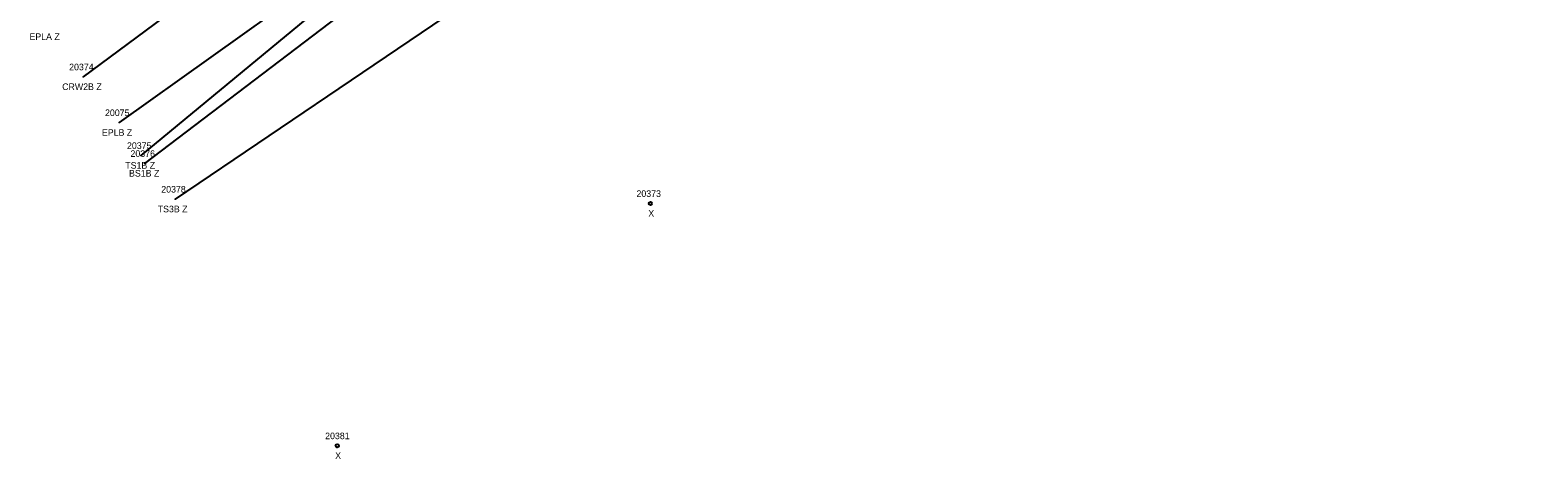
# Model space of a CAD drawing. Extents: x 1813127 to 1814107, y 1178171 to 1179078.
# Drawn here: x 1813574.7 to 1813803.8, y 1178408.6 to 1178473.8 of the extents above; entities that cross this region are included whole.
import ezdxf

# ---------------------------------------------------------------- set-up
doc = ezdxf.new("R2010")
doc.units = 0
for name, color, linetype in [('RD_DTM_BkLn1', 7, 'Continuous'), ('RD_DTM_BkLn2', 7, 'Continuous'), ('RD_EX_Road', 7, 'Continuous'), ('RD_EX_Road_txCode', 7, 'Continuous'), ('RD_SMD_Locator', 7, 'Continuous'), ('RD_SMD_Misc', 7, 'Continuous')]:
    doc.layers.add(name, color=color, linetype=linetype)

msp = doc.modelspace()

# ---------------------------------------------------------------- linework, layer by layer
at = {"layer": 'RD_DTM_BkLn1'}
msp.add_lwpolyline([(1813831.28, 1178643.33), (1813821.11, 1178637.41), (1813809.78, 1178629.12), (1813788.78, 1178614.79), (1813747.67, 1178586.85), (1813706.5, 1178558.14), (1813665.11, 1178528), (1813623.37, 1178496.83), (1813582.75, 1178466.66)], dxfattribs=at)
at = {"layer": 'RD_DTM_BkLn2'}
for points in [[(1813746.03, 1178561.9), (1813743.83, 1178564.42), (1813716.29, 1178544.93), (1813674.06, 1178515.49), (1813631.05, 1178487.38), (1813591.54, 1178454.7)], [(1813744.11, 1178561.57), (1813717.38, 1178543.56), (1813675.31, 1178513.46), (1813633, 1178484.68), (1813592.1, 1178453.49)], [(1813777.22, 1178536.25), (1813747.77, 1178553.49), (1813723.22, 1178536.36), (1813683.91, 1178504.3), (1813639.44, 1178476.94), (1813596.75, 1178448.06)]]:
    msp.add_lwpolyline(points, dxfattribs=at)
at = {"layer": 'RD_EX_Road'}
msp.add_lwpolyline([(1813815.99, 1178618.51), (1813795.14, 1178605.39), (1813756.93, 1178582.36), (1813736.74, 1178567), (1813712.58, 1178549.43), (1813670.71, 1178519.43), (1813630, 1178489.55), (1813588.23, 1178459.7)], dxfattribs=at)
at = {"layer": 'RD_SMD_Locator'}
for centre, radius in [((1813582.75, 1178466.66), 0.001), ((1813588.23, 1178459.7), 0.001), ((1813591.54, 1178454.7), 0.001), ((1813592.1, 1178453.49), 0.001), ((1813596.75, 1178448.06), 0.001), ((1813668.94, 1178447.4), 0.25), ((1813621.36, 1178410.56), 0.25)]:
    msp.add_circle(centre, radius, dxfattribs=at)

# ---------------------------------------------------------------- texts
at = {"layer": 'RD_EX_Road_txCode'}
for s, p in [('EPLA Z', (1813574.6, 1178472.27)), ('20075', (1813586.08, 1178460.7)), ('EPLB Z', (1813585.61, 1178457.7))]:
    msp.add_text(s, height=1, dxfattribs=at).set_placement(p)
at = {"layer": 'RD_SMD_Misc'}
for s, p in [('20374', (1813580.63, 1178467.66)), ('CRW2B Z', (1813579.57, 1178464.66)), ('20375', (1813589.42, 1178455.7)), ('20376', (1813589.95, 1178454.49)), ('TS1B Z', (1813589.16, 1178452.7)), ('BS1B Z', (1813589.73, 1178451.49)), ('20378', (1813594.63, 1178449.06)), ('20373', (1813666.83, 1178448.4)), ('TS3B Z', (1813594.09, 1178446.06)), ('X', (1813668.63, 1178445.4)), ('20381', (1813619.53, 1178411.56)), ('X', (1813621.05, 1178408.56))]:
    msp.add_text(s, height=1, dxfattribs=at).set_placement(p)

doc.saveas('drawing.dxf')
